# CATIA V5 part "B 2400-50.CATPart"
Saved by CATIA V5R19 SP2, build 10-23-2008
Part number: B 2400-50
Bounding box of the stored display mesh (mm): x -37.351 to 37.351, y -37.351 to 37.351, z 0 to 210
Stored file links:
  C:\Users\Bora\Desktop\3D Katı model\B serisi\B 2400\B 2400-50.CATPart
  C:\Program Files\Dassault Systemes\B19\intel_a\reffiles\standard\MetricThickPitch.txt
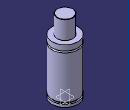
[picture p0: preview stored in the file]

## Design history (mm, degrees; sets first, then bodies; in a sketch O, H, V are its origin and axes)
Body1 (main body)
  Sketch1 on yz-plane, origin (0, 0, 0), H (0, 1, 0), V (0, 0, 1)
    point P3 (22.5, 209)
    point P5 (22.5, 209)
    point P10 (37.5, 136.5)
    point P11 (37.5, 141.5)
    point P13 (37.5, 141.5)
    point P14 (37.5, 136.5)
    line L1 (37.5, 0) -> (37.5, 8)
    line L2 (22.5, 209) -> (22.5, 157)
    arc A1 centre (21.5, 209) radius 1 from (22.5, 209) to (21.5, 210) ccw
    line L3 (33.5, 13) -> (33.5, 8)
    line L4 (37.5, 13) -> (37.5, 136.5)
    line L5 (37.5, 141.5) -> (37.5, 157)
    arc A2 centre (37.5, 139) radius 2.5 from (37.5, 141.5) to (37.5, 136.5) ccw
    line L6 (21.5, 210) -> (0, 210)
    point P15 (0, 210)
    line L7 (22.5, 157) -> (37.5, 157)
    line L8 (0, 0) -> (37.5, 0)
    line L9 (33.5, 13) -> (37.5, 13)
    line L10 (33.5, 8) -> (37.5, 8)
    coincidence: P15 V, P3 P5, P10 P14, P11 P13
    tangency: L6 A1
    horizontal: L7 H, L8 H, L9 H, L10 H
  Shaft1: profile Sketch1, axis Sketch1.V, angle 360
  Sketch2 on face of Shaft1 from Sketch1.L8, origin (0, 0, 0), H (1, 0, 0), V (0, -1, 0)
    point P1 (20, 0)
    distance P1 V = 20
  Hole1: placed by Sketch2, at (20, 0, 0) direction (0, 0, 1), diameter 6.647, depth 13, threaded "M8", thread diameter 8, thread depth 13, pitch 1.25
  CircPattern1: of Hole1, instances 4, angular step 90, axis from xy-plane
